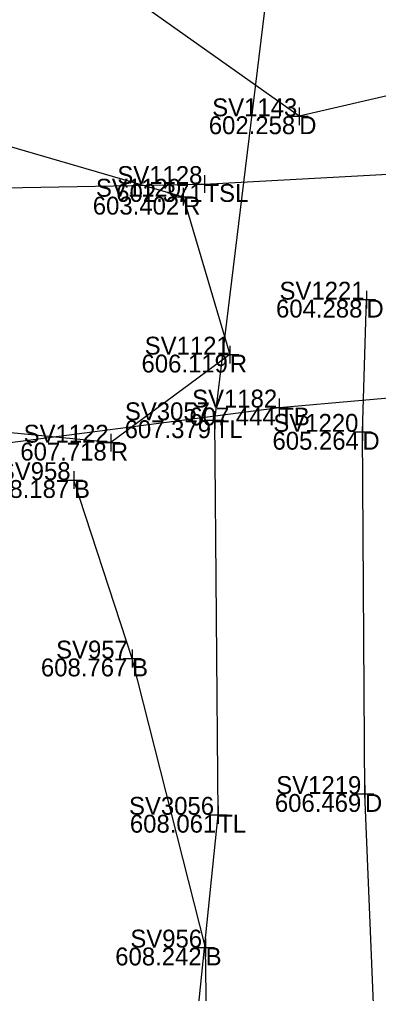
# Model space of a CAD drawing. Extents: x -2 to 1979875, y -2 to 232027.
# Drawn here: x 1978794.79 to 1978804.84, y 231234.17 to 231261.41 of the extents above; entities that cross this region are included whole.
import ezdxf

# ---------------------------------------------------------------- set-up
doc = ezdxf.new("R2010")
doc.units = 0
for name, color, linetype in [('_CIVIL_CONSTRUCTION', 7, 'Continuous'), ('DR_X_Ditch', 7, 'Continuous'), ('DR_X_Erosion_Control', 7, 'Continuous'), ('GE_P_Alignment', 7, 'Continuous'), ('GE_P_Alignment_1000_Curve_Data', 7, 'Continuous'), ('GE_X_Alignment', 7, 'Continuous'), ('GE_X_Alignment_100_Curve_Data', 7, 'Continuous'), ('GE_X_Alignment_100_Stations', 7, 'Continuous'), ('HY_X_Water_Edge', 7, 'Continuous'), ('SV_X_Toe_of_Slope', 7, 'Continuous'), ('SV_X_Top_of_Bank', 7, 'Continuous')]:
    doc.layers.add(name, color=color, linetype=linetype)

msp = doc.modelspace()

# ---------------------------------------------------------------- linework, layer by layer
at = {"layer": 'DR_X_Ditch'}
for points in [[(1978888.584, 231299.627), (1978879.993, 231287.447), (1978870.172, 231277.213), (1978856.534, 231274.917), (1978839.012, 231271.025), (1978823.007, 231263.425), (1978802.617, 231258.705), (1978787.259, 231269.564)], [(1978805.733, 231212.508), (1978804.96, 231227.558), (1978804.457, 231239.752), (1978804.385, 231249.881), (1978804.498, 231253.577)]]:
    msp.add_lwpolyline(points, dxfattribs=at)
at = {"layer": 'DR_X_Erosion_Control'}
msp.add_lwpolyline([(1978787.067, 231252.736), (1978788.074, 231256.704), (1978794.199, 231257.953), (1978799.369, 231256.456), (1978800.674, 231252.04), (1978797.344, 231249.578), (1978792.901, 231250.012), (1978792.436, 231252.197), (1978789.154, 231251.981)], close=True, dxfattribs=at)
at = {"layer": 'GE_P_Alignment'}
msp.add_lwpolyline([(1978782.883, 231095.387), (1978784.018, 231105.569), (1978783.215, 231126.435), (1978783.474, 231146.96), (1978785.203, 231170.705), (1978786.559, 231192.76), (1978790.09, 231207.457), (1978796.435, 231210.256), (1978800.205, 231220.321), (1978799.997, 231235.458), (1978797.94, 231243.541), (1978796.315, 231248.532)], dxfattribs=at)
at = {"layer": 'GE_P_Alignment_1000_Curve_Data'}
msp.add_lwpolyline([(1978791.661, 231060.333), (1978792.296, 231074.691), (1978791.754, 231088.963), (1978792.43, 231104.517), (1978792.032, 231117.838), (1978792.133, 231132.395), (1978792.905, 231147.152), (1978794.82, 231159.979), (1978795.624, 231173.18), (1978796.399, 231188.281), (1978796.48, 231201.342), (1978798.136, 231212.257), (1978799.055, 231226.533), (1978800.349, 231239.171), (1978800.253, 231250.204), (1978805.284, 231291.391)], dxfattribs=at)
at = {"layer": 'GE_X_Alignment_100_Curve_Data'}
for p, q in [((1978802.617, 231258.955), (1978802.617, 231258.455)), ((1978802.367, 231258.705), (1978802.867, 231258.705)), ((1978802.617, 231258.705), (1978802.617, 231258.705)), ((1978799.967, 231257.061), (1978799.967, 231256.561)), ((1978799.369, 231256.706), (1978799.369, 231256.206)), ((1978799.717, 231256.811), (1978800.217, 231256.811)), ((1978799.967, 231256.811), (1978799.967, 231256.811)), ((1978799.119, 231256.456), (1978799.619, 231256.456)), ((1978799.369, 231256.456), (1978799.369, 231256.456)), ((1978804.498, 231253.827), (1978804.498, 231253.327)), ((1978804.248, 231253.577), (1978804.748, 231253.577)), ((1978804.498, 231253.577), (1978804.498, 231253.577)), ((1978800.674, 231252.29), (1978800.674, 231251.79)), ((1978800.424, 231252.04), (1978800.924, 231252.04)), ((1978800.674, 231252.04), (1978800.674, 231252.04)), ((1978802.059, 231250.81), (1978802.059, 231250.31)), ((1978800.253, 231250.454), (1978800.253, 231249.954)), ((1978801.809, 231250.56), (1978802.309, 231250.56)), ((1978802.059, 231250.56), (1978802.059, 231250.56)), ((1978800.003, 231250.204), (1978800.503, 231250.204)), ((1978800.253, 231250.204), (1978800.253, 231250.204)), ((1978804.385, 231250.131), (1978804.385, 231249.631)), ((1978797.344, 231249.828), (1978797.344, 231249.328)), ((1978804.135, 231249.881), (1978804.635, 231249.881)), ((1978804.385, 231249.881), (1978804.385, 231249.881)), ((1978797.094, 231249.578), (1978797.594, 231249.578)), ((1978797.344, 231249.578), (1978797.344, 231249.578)), ((1978796.065, 231248.532), (1978796.565, 231248.532)), ((1978796.315, 231248.782), (1978796.315, 231248.282)), ((1978796.315, 231248.532), (1978796.315, 231248.532)), ((1978797.94, 231243.791), (1978797.94, 231243.291)), ((1978797.69, 231243.541), (1978798.19, 231243.541)), ((1978797.94, 231243.541), (1978797.94, 231243.541)), ((1978804.457, 231240.002), (1978804.457, 231239.502)), ((1978804.207, 231239.752), (1978804.707, 231239.752)), ((1978804.457, 231239.752), (1978804.457, 231239.752)), ((1978800.349, 231239.421), (1978800.349, 231238.921)), ((1978800.099, 231239.171), (1978800.599, 231239.171)), ((1978800.349, 231239.171), (1978800.349, 231239.171)), ((1978799.747, 231235.458), (1978800.247, 231235.458)), ((1978799.997, 231235.708), (1978799.997, 231235.208)), ((1978799.997, 231235.458), (1978799.997, 231235.458))]:
    msp.add_line(p, q, dxfattribs=at)
at = {"layer": 'HY_X_Water_Edge'}
msp.add_lwpolyline([(1978710.396, 231262.363), (1978725.371, 231260.246), (1978739.363, 231256.715), (1978742.039, 231254.081), (1978754.512, 231255.046), (1978783.289, 231254.287), (1978787.737, 231256.586), (1978799.967, 231256.811), (1978817.09, 231257.737), (1978832.082, 231262.479)], dxfattribs=at)
at = {"layer": 'SV_X_Toe_of_Slope'}
msp.add_lwpolyline([(1978783.289, 231254.287), (1978787.737, 231256.586), (1978799.967, 231256.811), (1978817.09, 231257.737), (1978832.082, 231262.479), (1978831.856, 231267.326), (1978861.367, 231270.387), (1978875.304, 231272.806), (1978884.386, 231282.392), (1978891.721, 231292.42), (1978902.966, 231322.566)], dxfattribs=at)
at = {"layer": 'SV_X_Top_of_Bank'}
msp.add_lwpolyline([(1978792.729, 231249.351), (1978802.059, 231250.56), (1978809.026, 231251.174), (1978824.702, 231257.152), (1978834.668, 231262.265), (1978843.76, 231264.082), (1978857.569, 231267.988), (1978870.834, 231267.898), (1978882.845, 231275.772), (1978894.192, 231280.826), (1978903.719, 231297.628)], dxfattribs=at)

# ---------------------------------------------------------------- texts
at = {"layer": '_CIVIL_CONSTRUCTION'}
for s, p in [('602.258', (1978800.087, 231258.205)), ('602.371', (1978797.497, 231256.311)), ('603.402', (1978796.841, 231255.956)), ('604.288', (1978801.968, 231253.077)), ('606.119', (1978798.205, 231251.54)), ('607.444', (1978799.543, 231250.06)), ('607.379', (1978797.732, 231249.704)), ('605.264', (1978801.869, 231249.381)), ('607.718', (1978794.814, 231249.078)), ('608.187', (1978793.764, 231248.032)), ('608.767', (1978795.389, 231243.041)), ('606.469', (1978801.936, 231239.252)), ('608.061', (1978797.879, 231238.671)), ('608.242', (1978797.469, 231234.958))]:
    msp.add_text(s, height=0.5, dxfattribs=at).set_placement(p)
at = {"layer": 'GE_X_Alignment'}
for s, p in [('SV1143', (1978800.183, 231258.705)), ('SV1128', (1978797.528, 231256.811)), ('SV1120', (1978796.929, 231256.456)), ('SV1221', (1978802.066, 231253.577)), ('SV1121', (1978798.294, 231252.04)), ('SV1182', (1978799.621, 231250.56)), ('SV3057', (1978797.74, 231250.204)), ('SV1220', (1978801.893, 231249.881)), ('SV1122', (1978794.906, 231249.578)), ('SV958', (1978794.212, 231248.532)), ('SV957', (1978795.815, 231243.541)), ('SV1219', (1978801.975, 231239.752)), ('SV3056', (1978797.855, 231239.171)), ('SV956', (1978797.892, 231235.458))]:
    msp.add_text(s, height=0.5, dxfattribs=at).set_placement(p)
at = {"layer": 'GE_X_Alignment_100_Stations'}
for s, p in [('D', (1978802.617, 231258.205)), ('TSL', (1978799.967, 231256.311)), ('R', (1978799.369, 231255.956)), ('D', (1978804.498, 231253.077)), ('R', (1978800.674, 231251.54)), ('TB', (1978802.059, 231250.06)), ('TL', (1978800.253, 231249.704)), ('D', (1978804.385, 231249.381)), ('R', (1978797.344, 231249.078)), ('B', (1978796.315, 231248.032)), ('B', (1978797.94, 231243.041)), ('D', (1978804.457, 231239.252)), ('TL', (1978800.349, 231238.671)), ('B', (1978799.997, 231234.958))]:
    msp.add_text(s, height=0.5, dxfattribs=at).set_placement(p)

doc.saveas('drawing.dxf')
